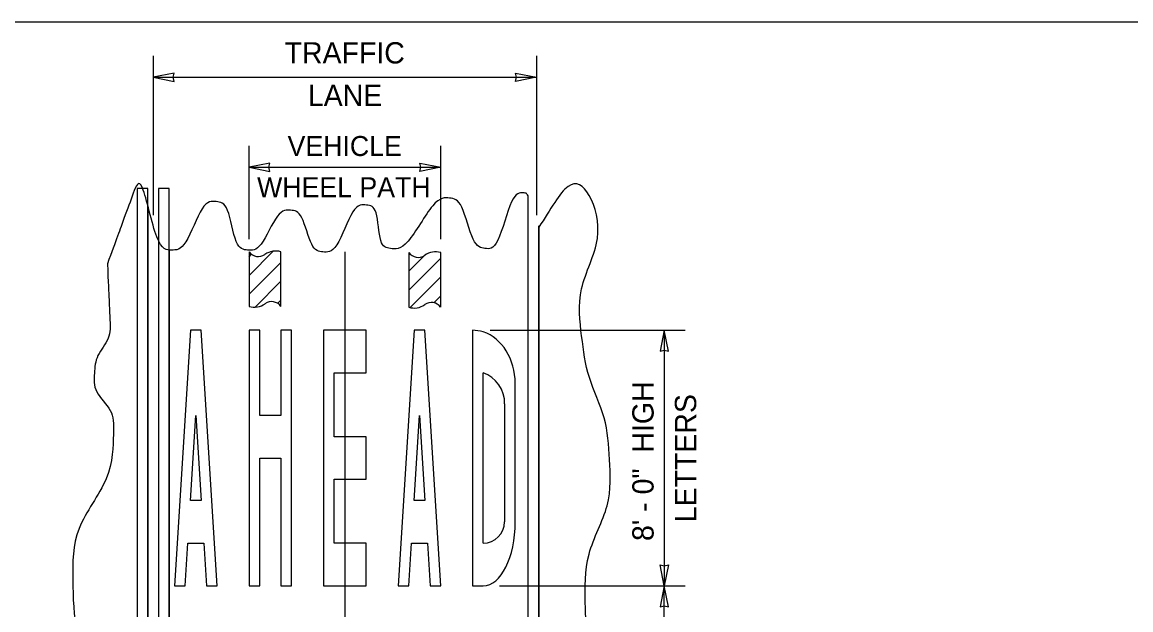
# Model space of a CAD drawing. Extents: x 99862 to 103151, y 100000 to 105076.
# Drawn here: x 101485 to 102318, y 104634 to 105076 of the extents above; entities that cross this region are included whole.
import ezdxf

# ---------------------------------------------------------------- set-up
doc = ezdxf.new("R2010")
doc.units = 0
for name, color, linetype in [('Level 1', 7, 'Continuous'), ('Level 15', 7, 'Continuous'), ('Level 2', 7, 'Continuous'), ('Level 20', 7, 'Continuous'), ('Level 3', 7, 'Continuous'), ('Level 6', 7, 'Continuous'), ('Level 8', 7, 'Continuous')]:
    doc.layers.add(name, color=color, linetype=linetype)

msp = doc.modelspace()

# ---------------------------------------------------------------- linework, layer by layer
at = {"layer": 'Level 1'}
msp.add_lwpolyline([(99862, 102999.5), (103151, 102999.5), (103151, 105075.5), (99862, 105075.5)], close=True, dxfattribs=at)
at = {"layer": 'Level 15'}
for p, q in [((101583.38, 105050.1), (101583.38, 104930.61)), ((101871.38, 105050.1), (101871.38, 104930.61)), ((101583.38, 105034.1), (101871.38, 105034.1)), ((101655.38, 104912.41), (101655.38, 104982.47)), ((101799.38, 104912.41), (101799.38, 104982.47)), ((101655.38, 104966.47), (101799.38, 104966.47)), ((101727.38, 104902.97), (101727.38, 104617.99)), ((101836.63, 104843.99), (101983.07, 104843.99)), ((101967.38, 104844.06), (101967.38, 104652.06)), ((101843.63, 104652.02), (101983.07, 104652.02)), ((101967.38, 104408.06), (101967.38, 104652.06))]:
    msp.add_line(p, q, dxfattribs=at)
for points in [[(101583.38, 105034.1), (101599.1, 105031.02), (101598.37, 105034.1), (101599.1, 105037.19)], [(101871.38, 105034.1), (101855.65, 105031.02), (101856.38, 105034.1), (101855.65, 105037.19)], [(101655.38, 104966.47), (101671.1, 104963.39), (101670.37, 104966.47), (101671.1, 104969.55)], [(101799.38, 104966.47), (101783.65, 104963.39), (101784.38, 104966.47), (101783.65, 104969.55)], [(101967.38, 104844.06), (101964.29, 104828.33), (101967.38, 104829.06), (101970.46, 104828.33)], [(101967.38, 104652.06), (101964.29, 104667.78), (101967.38, 104667.05), (101970.46, 104667.78)], [(101967.38, 104652.06), (101964.29, 104636.33), (101967.38, 104637.06), (101970.46, 104636.33)]]:
    msp.add_lwpolyline(points, close=True, dxfattribs=at)
at = {"layer": 'Level 2'}
for points in [[(101579.38, 104950.58), (101571.38, 104950.58), (101571.38, 104125.99)], [(101579.38, 104125.99), (101579.38, 104950.58)], [(101595.38, 104950.58), (101587.38, 104950.58), (101587.38, 104125.99)], [(101595.38, 104125.99), (101595.38, 104950.58)]]:
    msp.add_lwpolyline(points, dxfattribs=at)
at = {"layer": 'Level 3'}
msp.add_line((101865.17, 104923.64), (101865.17, 104923.64), dxfattribs=at)
for points in [[(101865.17, 104923.64), (101865.17, 104945.01)], [(101865.17, 104922.94), (101865.17, 104923.64)], [(101865.17, 104165.91), (101865.17, 104922.94)], [(101873.11, 104921.42), (101873.11, 104160.63)]]:
    msp.add_lwpolyline(points, dxfattribs=at)
for points in [[(101865.17, 104945.01), (101864.37, 104946.31), (101863.47, 104947.1), (101862.42, 104947.18), (101852.66, 104947.9), (101842.33, 104904.2), (101832.5, 104905.56), (101823.72, 104906.76), (101815.31, 104942.25), (101806.49, 104943.27), (101795.11, 104944.6), (101773.29, 104903.83), (101760.97, 104905.56), (101753.33, 104906.62), (101751.89, 104937.09), (101744.06, 104938.07), (101733.69, 104939.37), (101720.86, 104901.82), (101710.57, 104902.95), (101702.25, 104903.87), (101695.26, 104933.4), (101686.83, 104934.17), (101677.33, 104935.04), (101663.76, 104903.42), (101654.31, 104904.25), (101645.06, 104905.08), (101639.93, 104939.72), (101630.9, 104940.67), (101620.54, 104941.77), (101607.53, 104904.2), (101597.09, 104904.25), (101586.25, 104904.32), (101574.38, 104963.32), (101568.47, 104947.18), (101561.97, 104929.4), (101555.47, 104911.63), (101548.96, 104893.85)], [(101914.31, 104163.65), (101915.01, 104174.54), (101913.96, 104185.47), (101913.24, 104202.68), (101911.86, 104228.26), (101905.5, 104253.93), (101905.44, 104279.41), (101905.4, 104299.42), (101919.97, 104318.03), (101921.05, 104337.94), (101923.27, 104378.84), (101905.56, 104420.64), (101906.74, 104461.5), (101907.7, 104494.52), (101924.67, 104527.52), (101924.95, 104560.35), (101925.17, 104586.02), (101908.62, 104611.42), (101908.04, 104637.09), (101907.24, 104676.44), (101928.32, 104712.3), (101926.25, 104747.74), (101924.47, 104778.34), (101909.21, 104808.44), (101905.44, 104838.79), (101900.97, 104874.78), (101922.46, 104913.37), (101911.94, 104949.34), (101895.93, 104960.32), (101881.85, 104934.63), (101873.11, 104921.42)], [(101548.96, 104893.85), (101549.61, 104879.76), (101550.26, 104865.67), (101550.91, 104851.58), (101551.55, 104837.81), (101540.11, 104825.02), (101539.21, 104811.91), (101538.24, 104797.76), (101553.69, 104783.84), (101553.51, 104769.64), (101553.05, 104732.54), (101522.5, 104695.27), (101522.95, 104657.13), (101523.4, 104615.42), (101545.19, 104577.7), (101545.06, 104539.98), (101544.87, 104486.65), (101512.5, 104433.32), (101513.85, 104380), (101514.67, 104347.51), (101538.79, 104316.22), (101538.23, 104283.75), (101537.69, 104252.36), (101525.85, 104220.45), (101524.25, 104182.29), (101523.61, 104172.05), (101522.88, 104164.24), (101523.38, 104156.8)]]:
    msp.add_open_spline(points, degree=3, dxfattribs=at)
at = {"layer": 'Level 6'}
for p, q in [((101865.16, 104166.54), (101865.17, 104944.92)), ((101873.16, 104161.48), (101873.17, 104922.42)), ((101655.38, 104885.16), (101673.6, 104903.38)), ((101655.38, 104902.97), (101655.38, 104861.97)), ((101655.38, 104899.3), (101657.23, 104901.16)), ((101775.38, 104902.37), (101775.38, 104861.37)), ((101775.38, 104888.33), (101787.47, 104900.43)), ((101775.38, 104874.19), (101799.38, 104898.19)), ((101799.38, 104861.37), (101799.38, 104902.37)), ((101655.38, 104871.02), (101679.38, 104895.02)), ((101659.93, 104861.44), (101679.38, 104880.88)), ((101776.49, 104861.16), (101799.38, 104884.04)), ((101676.85, 104864.21), (101679.38, 104866.74)), ((101794.13, 104864.66), (101799.38, 104869.9))]:
    msp.add_line(p, q, dxfattribs=at)
for points in [[(101571.27, 104949.9), (101571.27, 104145)], [(101579.38, 104935.95), (101579.38, 104133.16)], [(101587.39, 104916.25), (101587.39, 104136.33)], [(101595.35, 104904.77), (101595.35, 104142.89)], [(101679.38, 104861.97), (101679.38, 104902.97)]]:
    msp.add_lwpolyline(points, dxfattribs=at)
for centre, radius, start, end in [((101662.4, 104908.12), 8.71, 216.245, 304.83036), ((101675.38, 104889.97), 13.6, 72.89727, 126.02737), ((101782.4, 104907.52), 8.71, 216.245, 304.83036), ((101795.38, 104889.37), 13.6, 72.89727, 126.02737), ((101659.45, 104874.55), 13.23, 252.07882, 306.84583), ((101672.35, 104856.82), 8.71, 36.245, 124.83036), ((101779.45, 104873.95), 13.23, 252.07882, 306.84583), ((101792.35, 104856.22), 8.71, 36.245, 124.83036)]:
    msp.add_arc(centre, radius, start, end, dxfattribs=at)
at = {"layer": 'Level 8'}
for p, q in [((101611.38, 104844.02), (101599.38, 104652.02)), ((101619.38, 104844.02), (101611.38, 104844.02)), ((101631.38, 104652.02), (101619.38, 104844.02)), ((101823.38, 104844.02), (101823.38, 104788.77)), ((101831.38, 104788.77), (101831.38, 104812.02)), ((101855.38, 104788.77), (101855.38, 104804.02)), ((101823.38, 104788.77), (101823.38, 104788.02)), ((101823.38, 104788.02), (101823.38, 104708.02)), ((101831.38, 104788.02), (101831.38, 104788.77)), ((101831.38, 104708.02), (101831.38, 104788.02)), ((101847.42, 104788.77), (101847.38, 104788.02)), ((101847.38, 104788.02), (101847.38, 104708.02)), ((101855.38, 104788.02), (101855.38, 104788.77)), ((101855.38, 104708.02), (101855.38, 104788.02)), ((101611.38, 104716.02), (101615.38, 104780.02)), ((101615.38, 104780.02), (101619.38, 104716.02)), ((101779.38, 104716.02), (101783.38, 104780.02)), ((101783.38, 104780.02), (101787.38, 104716.02)), ((101619.38, 104716.02), (101611.38, 104716.02)), ((101787.38, 104716.02), (101779.38, 104716.02)), ((101823.38, 104708.02), (101823.38, 104707.02)), ((101823.38, 104707.02), (101823.38, 104652.02)), ((101831.38, 104707.02), (101831.38, 104708.02)), ((101831.38, 104684.02), (101831.38, 104707.02)), ((101847.38, 104708.02), (101847.38, 104707.02)), ((101847.38, 104707.02), (101847.38, 104700.02)), ((101855.38, 104707.02), (101855.38, 104708.02)), ((101855.38, 104700.02), (101855.38, 104707.02)), ((101607.38, 104652.02), (101609.38, 104684.02)), ((101609.38, 104684.02), (101621.38, 104684.02)), ((101621.38, 104684.02), (101623.38, 104652.02)), ((101599.38, 104652.02), (101607.38, 104652.02)), ((101623.38, 104652.02), (101631.38, 104652.02)), ((101823.38, 104652.02), (101831.38, 104652.02))]:
    msp.add_line(p, q, dxfattribs=at)
for points in [[(101607.38, 104652.02), (101609.38, 104684.02), (101621.38, 104684.02), (101623.38, 104652.02), (101631.38, 104652.02), (101619.38, 104844.02), (101611.38, 104844.02), (101599.38, 104652.02), (101607.38, 104652.02)], [(101607.38, 104652.02), (101609.38, 104684.02), (101621.38, 104684.02), (101623.38, 104652.02), (101631.38, 104652.02), (101619.38, 104844.02), (101611.38, 104844.02), (101599.38, 104652.02), (101607.38, 104652.02)], [(101679.38, 104844.02), (101679.38, 104780.02), (101663.38, 104780.02), (101663.38, 104844.02), (101655.38, 104844.02), (101655.38, 104652.02), (101663.38, 104652.02), (101663.38, 104748.02), (101679.38, 104748.02), (101679.38, 104652.02), (101687.38, 104652.02), (101687.38, 104844.02), (101679.38, 104844.02)], [(101687.38, 104652.02), (101687.38, 104844.02), (101679.38, 104844.02), (101679.38, 104780.02), (101663.38, 104780.02), (101663.38, 104844.02), (101655.38, 104844.02), (101655.38, 104652.02), (101663.38, 104652.02), (101663.38, 104748.02), (101679.38, 104748.02), (101679.38, 104652.02), (101687.38, 104652.02)], [(101719.38, 104684.02), (101719.38, 104732.02), (101743.38, 104732.02), (101743.38, 104764.02), (101719.38, 104764.02), (101719.38, 104812.02), (101743.38, 104812.02), (101743.38, 104844.02), (101719.38, 104844.02), (101715.38, 104844.02), (101711.38, 104844.02), (101711.38, 104652.02), (101717.38, 104652.02), (101719.38, 104652.02), (101743.38, 104652.02), (101743.38, 104684.02), (101719.38, 104684.02)], [(101743.38, 104684.02), (101719.38, 104684.02), (101719.38, 104732.02), (101743.38, 104732.02), (101743.38, 104764.02), (101719.38, 104764.02), (101719.38, 104812.02), (101743.38, 104812.02), (101743.38, 104844.02), (101719.38, 104844.02), (101715.38, 104844.02), (101711.38, 104844.02), (101711.38, 104652.02), (101717.38, 104652.02), (101719.38, 104652.02), (101743.38, 104652.02), (101743.38, 104684.02)], [(101775.38, 104652.02), (101777.38, 104684.02), (101789.38, 104684.02), (101791.38, 104652.02), (101799.38, 104652.02), (101787.38, 104844.02), (101779.38, 104844.02), (101767.38, 104652.02), (101775.38, 104652.02)], [(101767.38, 104652.02), (101775.38, 104652.02), (101777.38, 104684.02), (101789.38, 104684.02), (101791.38, 104652.02), (101799.38, 104652.02), (101787.38, 104844.02), (101779.38, 104844.02), (101767.38, 104652.02)], [(101823.38, 104844.02), (101823.38, 104788.77), (101823.38, 104788.02), (101823.38, 104708.02), (101823.38, 104707.02), (101823.38, 104652.02), (101831.38, 104652.02)], [(101823.38, 104844.02), (101823.38, 104788.77), (101823.38, 104788.02), (101823.38, 104708.02), (101823.38, 104707.02)], [(101831.38, 104684.02), (101831.38, 104707.02), (101831.38, 104708.02), (101831.38, 104788.02), (101831.38, 104788.77), (101831.38, 104812.02)], [(101831.38, 104684.02), (101831.38, 104707.02), (101831.38, 104708.02), (101831.38, 104788.02), (101831.38, 104788.77), (101831.38, 104812.02)], [(101855.38, 104700.02), (101855.38, 104707.02), (101855.38, 104708.02), (101855.38, 104788.02), (101855.38, 104788.77), (101855.38, 104804.02)], [(101855.38, 104700.02), (101855.38, 104707.02), (101855.38, 104708.02), (101855.38, 104788.02), (101855.38, 104788.77), (101855.38, 104804.02)], [(101847.42, 104788.77), (101847.38, 104788.02), (101847.38, 104708.02), (101847.38, 104707.02), (101847.38, 104700.02)], [(101847.42, 104788.77), (101847.38, 104788.02), (101847.38, 104708.02), (101847.38, 104707.02), (101847.38, 104700.02)], [(101619.38, 104716.02), (101611.38, 104716.02), (101615.38, 104780.02), (101619.38, 104716.02)], [(101783.38, 104780.02), (101787.38, 104716.02), (101779.38, 104716.02), (101783.38, 104780.02)], [(101823.38, 104707.02), (101823.38, 104652.02), (101831.38, 104652.02)]]:
    msp.add_lwpolyline(points, dxfattribs=at)
for points in [[(101679.38, 104780.02), (101663.38, 104780.02), (101663.38, 104844.02), (101655.38, 104844.02), (101655.38, 104652.02), (101663.38, 104652.02), (101663.38, 104748.02), (101679.38, 104748.02), (101679.38, 104652.02), (101687.38, 104652.02), (101687.38, 104844.02), (101679.38, 104844.02)], [(101719.38, 104732.02), (101743.38, 104732.02), (101743.38, 104764.02), (101719.38, 104764.02), (101719.38, 104812.02), (101743.38, 104812.02), (101743.38, 104844.02), (101719.38, 104844.02), (101715.38, 104844.02), (101711.38, 104844.02), (101711.38, 104652.02), (101717.38, 104652.02), (101719.38, 104652.02), (101743.38, 104652.02), (101743.38, 104684.02), (101719.38, 104684.02)], [(101777.38, 104684.02), (101789.38, 104684.02), (101791.38, 104652.02), (101799.38, 104652.02), (101787.38, 104844.02), (101779.38, 104844.02), (101767.38, 104652.02), (101775.38, 104652.02)]]:
    msp.add_lwpolyline(points, close=True, dxfattribs=at)
msp.add_arc((101831.38, 104700.02), 16, 270, 0, dxfattribs=at)
msp.add_arc((101831.38, 104700.02), 16, 270, 0, dxfattribs=at)
for centre, major_axis, ratio, start_param, end_param in [((101823.38, 104804.02), (0, -40), 0.8, 2.888912, 3.141593), ((101823.38, 104804.02), (0, -40), 0.8, 2.888912, 3.141593), ((101823.38, 104804.02), (0, -40), 0.8, 1.570796, 2.888912), ((101823.38, 104804.02), (0, -40), 0.8, 1.570796, 2.888912), ((101829.96, 104793.74), (11.31, -16.97), 0.784465, 0.826187, 2.356194), ((101829.96, 104793.74), (11.31, -16.97), 0.784465, 0.826187, 2.356194), ((101831.38, 104700.02), (0, -48), 0.5, 0, 1.570796), ((101831.38, 104700.02), (0, -48), 0.5, 0, 1.570796)]:
    msp.add_ellipse(centre, major_axis=major_axis, ratio=ratio, start_param=start_param, end_param=end_param, dxfattribs=at)

# ---------------------------------------------------------------- texts
at = {"layer": 'Level 20'}
for s, height, rotation, p in [('TRAFFIC', 16, 360, (101682.11, 105044.47)), ('LANE', 16, 360, (101699.6, 105012.47)), ('VEHICLE', 15, 360, (101684.35, 104974.97)), ('WHEEL PATH', 15, 360, (101661.44, 104943.97)), ('8\' - 0"  HIGH', 16, 90, (101959.38, 104685.69)), ('LETTERS', 16, 90, (101991.38, 104699.76))]:
    msp.add_text(s, height=height, rotation=rotation, dxfattribs=at).set_placement(p)

doc.saveas('drawing.dxf')
